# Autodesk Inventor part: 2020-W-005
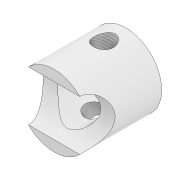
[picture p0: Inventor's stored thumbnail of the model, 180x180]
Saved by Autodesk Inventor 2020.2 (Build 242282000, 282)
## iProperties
Manager: www.cadconsulting.pl
Company: Fabian Stasiak CAD Consulting
Created: 2019-11
Part Number: 2020-W-005
Material: Tworzywo sztuczne ABS
Document SubType Name: Modeling
Designer: F.Stasiak
Density: 1.06 g/cm^3
Appearance: Gładki — biały
Author: F.Stasiak
Subject: Zbiór ćwiczeń. Autodesk Inventor 2020. Kurs podstawowy
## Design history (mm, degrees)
sketch "Szkic1"
  geometry: C1 r 25 at (0, 0); C2 r 15 at (0, 0); 1 further point
  constraints: 2 centre point, 2 coincident
  dimensions: "d0" = 50 diameter of C1; "d1" = 30 diameter of C2
extrude "Wyciągnięcie proste1" new body sketch "Szkic1" stored distance "d2" = 50; taper "d3" = 0 deg
node "Płaszczyzna konstrukcyjna1"
sketch "Szkic2"
  geometry: L1 (0, -35)-(0, 35) reference; L2 (10, -10)-(-10, -10); L3 (-25, -25)-(25, -25) reference; 2 further points
  constraints: 2 end point, 1 horizontal, 1 midpoint, 1 point on line
  dimensions: "d4" = 20 distance of L2.start L2.end; "d5" = 15 distance between parallel lines of L3 L2
node "Płaszczyzna konstrukcyjna2"
node "Punkt konstrukcyjny1"
node "Oś konstrukcyjna1"
  node "Płaszczyzna konstrukcyjna3"
hole "Otwór1" diameter "d10" = 13.3762; stored, may be unused: countersink angle "d14" = 90 deg, drill point angle "d16" = 118 deg; dims "d11" = 30, "d12" = 4, "d13" = 2, "d15" = 8, "d22" = 10, "d23" = 10
mirror "Odbij1"
sketch "Szkic3"
  geometry: L1 (-15, 25)-(15, 25) reference; L2 (25, 25)-(-25, 25) reference; C1 r 17.5 at (0, 25); 1 further point
  constraints: 1 centre point, 1 midpoint
  dimensions: "d19" = 35 diameter of C1
extrude "Wyciągnięcie proste2" cut sketch "Szkic3" stored distance "d20" = 50; taper "d21" = 0 deg
node "Bryła1"
other parameters: "d6" = 60 deg, "d7" = 90 deg
